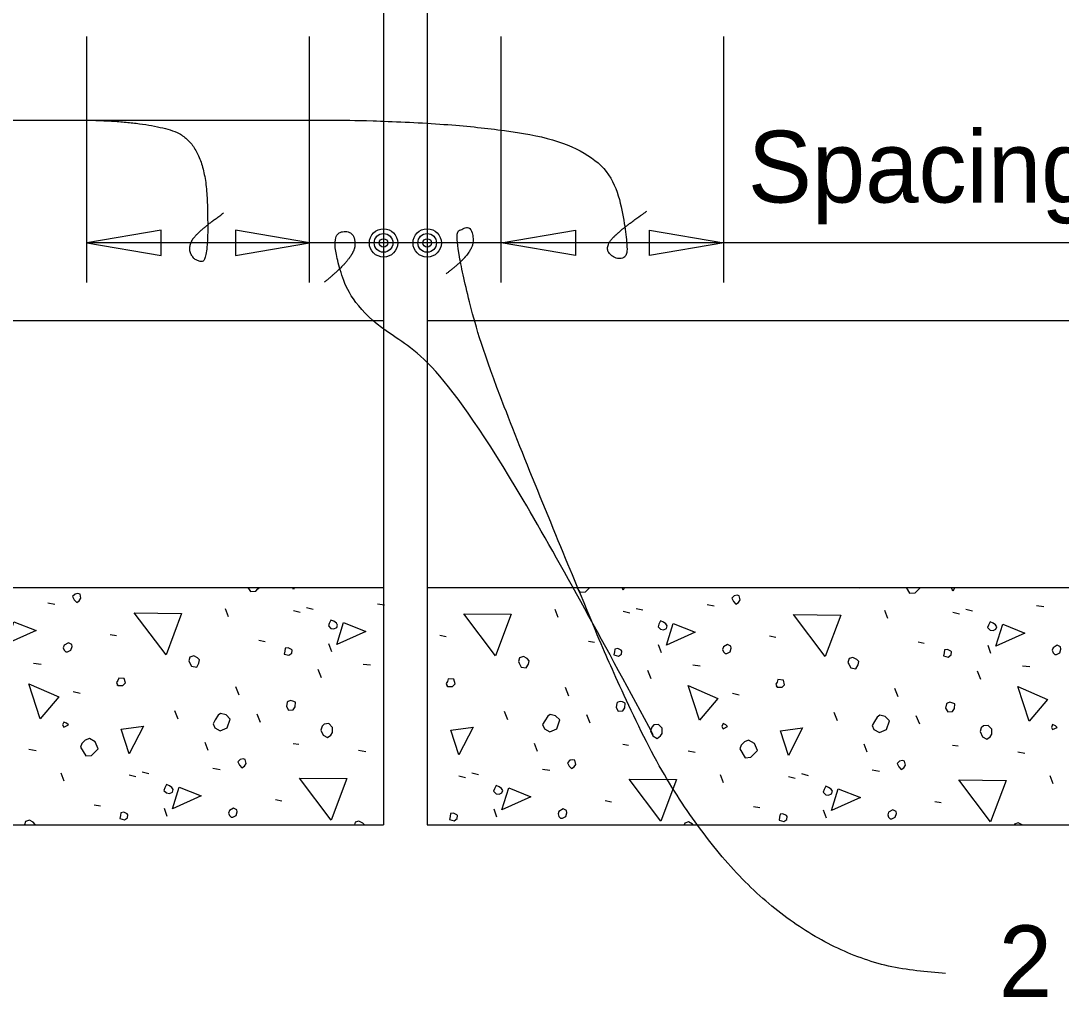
# Model space of a CAD drawing. Extents: x 0 to 20.5, y 0 to 13.
# Drawn here: x 12.283 to 13.744, y 8.997 to 10.367 of the extents above; entities that cross this region are included whole.
import ezdxf

# ---------------------------------------------------------------- set-up
doc = ezdxf.new("R2010")
doc.units = 0
for name, color, linetype in [('Dimension', 7, 'Continuous'), ('Miscellaneous', 7, 'Continuous'), ('TextStructures', 7, 'Continuous'), ('TrafBarrierConc', 7, 'Continuous')]:
    doc.layers.add(name, color=color, linetype=linetype)

msp = doc.modelspace()

# ---------------------------------------------------------------- linework, layer by layer
at = {"layer": 'Dimension'}
for p, q in [((12.3757, 9.9998), (12.3757, 10.3453)), ((12.6882, 9.9998), (12.6882, 10.3453)), ((12.9577, 9.9998), (12.9577, 10.3453)), ((13.2702, 9.9998), (13.2702, 10.3453)), ((15.3216, 10.0556), (12.3757, 10.0556))]:
    msp.add_line(p, q, dxfattribs=at)
for points in [[(12.3757, 10.0556), (12.4798, 10.038), (12.4798, 10.0733)], [(12.6882, 10.0556), (12.5841, 10.0733), (12.5841, 10.038)], [(12.9577, 10.0556), (13.0619, 10.0733), (13.0619, 10.038)], [(13.2702, 10.0556), (13.1661, 10.038), (13.1661, 10.0733)]]:
    msp.add_lwpolyline(points, close=True, dxfattribs=at)
for centre, radius in [((12.7923, 10.0556), 0.0199), ((12.8536, 10.0556), 0.0199), ((12.7923, 10.0556), 0.0131), ((12.7923, 10.0556), 0.00592), ((12.8536, 10.0556), 0.0131), ((12.8536, 10.0556), 0.00592)]:
    msp.add_circle(centre, radius, dxfattribs=at)
for points in [[(12.1713, 10.2281), (12.2987, 10.2281), (12.5124, 10.2281), (12.8773, 10.2281), (13.1083, 10.1892), (13.1396, 10.0428), (13.1234, 10.0299), (13.1018, 10.0461), (13.1212, 10.072), (13.1622, 10.1001)], [(12.3581, 10.2281), (12.4466, 10.2281), (12.5416, 10.1995), (12.5476, 10.0296), (12.5271, 10.0296), (12.5174, 10.0485), (12.5298, 10.0707), (12.5676, 10.0977)], [(13.1712, 9.3651), (12.9166, 9.8494), (12.7505, 9.9604), (12.7241, 10.0392), (12.7241, 10.0716), (12.7522, 10.0716), (12.7522, 10.0349), (12.709, 10.0004)], [(13.582, 9.0297), (13.2936, 9.0378), (12.9412, 9.859), (12.8911, 10.0619), (12.9019, 10.077), (12.9181, 10.077), (12.9181, 10.0403), (12.8803, 10.0123)]]:
    msp.add_open_spline(points, degree=2, dxfattribs=at)
at = {"layer": 'Miscellaneous'}
for p, q in [((13.4589, 9.5719), (13.4612, 9.5714)), ((13.7028, 9.5714), (13.7026, 9.5719)), ((12.3206, 9.5502), (12.3306, 9.5485)), ((12.7837, 9.549), (12.7937, 9.5473)), ((13.2468, 9.5479), (13.2568, 9.5461)), ((13.7098, 9.5467), (13.7199, 9.5449)), ((12.5746, 9.5308), (12.5704, 9.542)), ((12.6659, 9.5396), (12.6753, 9.5373)), ((12.6841, 9.5437), (12.6936, 9.5413)), ((13.0376, 9.5296), (13.0335, 9.5408)), ((13.129, 9.5384), (13.1384, 9.5361)), ((13.1472, 9.5425), (13.1566, 9.5402)), ((13.5007, 9.5284), (13.4966, 9.5396)), ((13.5921, 9.5373), (13.6015, 9.5349)), ((13.6103, 9.5413), (13.6197, 9.539)), ((12.4084, 9.506), (12.4172, 9.5043)), ((12.8715, 9.5049), (12.8803, 9.5031)), ((13.3346, 9.5037), (13.3434, 9.5019)), ((12.617, 9.4978), (12.6258, 9.496)), ((12.7195, 9.4813), (12.7154, 9.4925)), ((13.0801, 9.4966), (13.0889, 9.4948)), ((13.1826, 9.4801), (13.1784, 9.4913)), ((13.5432, 9.4954), (13.552, 9.4937)), ((13.6456, 9.479), (13.6415, 9.4902)), ((12.3006, 9.4654), (12.3112, 9.4642)), ((12.7053, 9.4448), (12.7006, 9.4566)), ((12.7636, 9.4642), (12.7742, 9.463)), ((13.2267, 9.463), (13.2373, 9.4618)), ((13.6898, 9.4618), (13.7004, 9.4607)), ((13.1684, 9.4436), (13.1637, 9.4554)), ((13.6315, 9.4424), (13.6268, 9.4542)), ((12.5893, 9.4206), (12.5846, 9.4324)), ((13.0524, 9.4194), (13.0477, 9.4312)), ((13.5155, 9.4182), (13.5107, 9.43)), ((12.3565, 9.4259), (12.366, 9.4235)), ((13.2827, 9.4235), (13.2921, 9.4212)), ((12.5039, 9.387), (12.4991, 9.3988)), ((12.6193, 9.3823), (12.6146, 9.3941)), ((12.9669, 9.3858), (12.9622, 9.3976)), ((13.0824, 9.3811), (13.0777, 9.3929)), ((13.43, 9.3846), (13.4253, 9.3964)), ((13.5455, 9.38), (13.5408, 9.3918)), ((12.2941, 9.3446), (12.3041, 9.3428)), ((12.5457, 9.3428), (12.5416, 9.354)), ((12.6653, 9.3529), (12.6735, 9.3517)), ((12.7572, 9.3434), (12.7672, 9.3417)), ((13.0088, 9.3416), (13.0046, 9.3528)), ((13.1284, 9.3517), (13.1366, 9.3505)), ((13.2203, 9.3423), (13.2303, 9.3405)), ((13.4719, 9.3405), (13.4677, 9.3516)), ((13.5914, 9.3505), (13.5997, 9.3493)), ((13.6834, 9.3411), (13.6934, 9.3393)), ((12.3436, 9.2998), (12.3395, 9.311)), ((12.4532, 9.3128), (12.4626, 9.3104)), ((12.5527, 9.3181), (12.5627, 9.3163)), ((12.9163, 9.3116), (12.9257, 9.3092)), ((13.0158, 9.3169), (13.0258, 9.3151)), ((13.3793, 9.3104), (13.3888, 9.308)), ((13.4789, 9.3157), (13.4889, 9.314)), ((12.4349, 9.3087), (12.4444, 9.3063)), ((12.898, 9.3075), (12.9075, 9.3051)), ((13.2698, 9.2975), (13.2656, 9.3087)), ((13.3611, 9.3063), (13.3705, 9.304)), ((13.7329, 9.2963), (13.7287, 9.3075)), ((12.386, 9.2668), (12.3949, 9.2651)), ((12.6405, 9.2739), (12.6494, 9.2721)), ((13.1036, 9.2727), (13.1124, 9.271)), ((13.5667, 9.2715), (13.5755, 9.2698)), ((12.4885, 9.2504), (12.4844, 9.2616)), ((12.9516, 9.2492), (12.9475, 9.2604)), ((13.3122, 9.2645), (13.321, 9.2627)), ((13.4147, 9.248), (13.4106, 9.2592))]:
    msp.add_line(p, q, dxfattribs=at)
for points in [[(12.3577, 9.5544), (12.3613, 9.5508), (12.3648, 9.5532), (12.3671, 9.5567), (12.366, 9.5626), (12.363, 9.5632), (12.3589, 9.5626), (12.3554, 9.5591), (12.3577, 9.5544)], [(12.6017, 9.5719), (12.6052, 9.5661), (12.6129, 9.5667), (12.6158, 9.5697), (12.618, 9.5719)], [(12.6659, 9.569), (12.665, 9.5719)], [(12.6673, 9.5719), (12.6659, 9.569)], [(13.064, 9.5719), (13.0683, 9.565), (13.0759, 9.5655), (13.0789, 9.5685), (13.0823, 9.5719)], [(13.1289, 9.5679), (13.1277, 9.5719)], [(13.131, 9.5719), (13.1289, 9.5679)], [(13.2839, 9.552), (13.2874, 9.5485), (13.291, 9.5508), (13.2933, 9.5544), (13.2921, 9.5602), (13.2892, 9.5608), (13.2851, 9.5602), (13.2815, 9.5567), (13.2839, 9.552)], [(13.5264, 9.5719), (13.5314, 9.5638), (13.539, 9.5644), (13.542, 9.5673), (13.5465, 9.5719)], [(13.592, 9.5667), (13.5904, 9.5719)], [(13.5947, 9.5719), (13.592, 9.5667)], [(12.4868, 9.4772), (12.442, 9.5361), (12.5086, 9.5355), (12.4868, 9.4772)], [(12.9498, 9.476), (12.9051, 9.5349), (12.9716, 9.5343), (12.9498, 9.476)], [(13.4129, 9.4748), (13.3681, 9.5337), (13.4347, 9.5331), (13.4129, 9.4748)], [(12.2634, 9.4931), (12.2729, 9.5237), (12.3041, 9.5113), (12.2634, 9.4931)], [(12.7183, 9.5142), (12.7224, 9.5137), (12.7266, 9.5154), (12.7277, 9.519), (12.726, 9.5219), (12.7224, 9.5243), (12.7183, 9.526), (12.7159, 9.5213), (12.7148, 9.5178), (12.7183, 9.5142)], [(12.7265, 9.4919), (12.7359, 9.5225), (12.7672, 9.5102), (12.7265, 9.4919)], [(13.1814, 9.5131), (13.1855, 9.5125), (13.1896, 9.5142), (13.1908, 9.5178), (13.189, 9.5207), (13.1855, 9.5231), (13.1814, 9.5249), (13.179, 9.5201), (13.1779, 9.5166), (13.1814, 9.5131)], [(13.1896, 9.4907), (13.199, 9.5214), (13.2303, 9.509), (13.1896, 9.4907)], [(13.6445, 9.5119), (13.6486, 9.5113), (13.6527, 9.5131), (13.6539, 9.5166), (13.6521, 9.5195), (13.6486, 9.5219), (13.6445, 9.5237), (13.6421, 9.519), (13.6409, 9.5154), (13.6445, 9.5119)], [(13.6527, 9.4895), (13.6621, 9.5202), (13.6933, 9.5078), (13.6527, 9.4895)], [(12.3459, 9.4813), (12.3483, 9.4813), (12.353, 9.4836), (12.3548, 9.4889), (12.3542, 9.4919), (12.3495, 9.4942), (12.3436, 9.4907), (12.3424, 9.4872), (12.3436, 9.4836), (12.3459, 9.4813)], [(12.6529, 9.4783), (12.6594, 9.4766), (12.6635, 9.4795), (12.6641, 9.4836), (12.663, 9.4848), (12.6582, 9.4872), (12.6541, 9.4866), (12.6535, 9.4825), (12.6529, 9.4783)], [(13.116, 9.4772), (13.1225, 9.4754), (13.1266, 9.4783), (13.1272, 9.4825), (13.126, 9.4836), (13.1213, 9.486), (13.1172, 9.4854), (13.1166, 9.4813), (13.116, 9.4772)], [(13.2721, 9.4789), (13.2745, 9.4789), (13.2792, 9.4813), (13.2809, 9.4866), (13.2803, 9.4895), (13.2756, 9.4919), (13.2697, 9.4884), (13.2686, 9.4848), (13.2697, 9.4813), (13.2721, 9.4789)], [(13.7352, 9.4777), (13.7375, 9.4777), (13.7422, 9.4801), (13.744, 9.4854), (13.7434, 9.4884), (13.7387, 9.4907), (13.7328, 9.4872), (13.7316, 9.4836), (13.7328, 9.4801), (13.7352, 9.4777)], [(12.5198, 9.4666), (12.5227, 9.4612), (12.5298, 9.4601), (12.5327, 9.4654), (12.5339, 9.4701), (12.531, 9.473), (12.5257, 9.476), (12.5204, 9.4742), (12.5186, 9.4689), (12.5198, 9.4666)], [(12.9828, 9.4654), (12.9858, 9.4601), (12.9929, 9.4589), (12.9958, 9.4642), (12.997, 9.4689), (12.994, 9.4719), (12.9887, 9.4748), (12.9834, 9.473), (12.9817, 9.4677), (12.9828, 9.4654)], [(13.4459, 9.4642), (13.4489, 9.4589), (13.4559, 9.4577), (13.4589, 9.463), (13.4601, 9.4677), (13.4571, 9.4707), (13.4518, 9.4736), (13.4465, 9.4719), (13.4447, 9.4666), (13.4459, 9.4642)], [(13.5791, 9.476), (13.5856, 9.4742), (13.5897, 9.4772), (13.5903, 9.4813), (13.5891, 9.4825), (13.5844, 9.4848), (13.5803, 9.4842), (13.5797, 9.4801), (13.5791, 9.476)], [(12.419, 9.4341), (12.4261, 9.4341), (12.4296, 9.4377), (12.4278, 9.4442), (12.4202, 9.4447), (12.419, 9.4412), (12.4172, 9.4383), (12.419, 9.4341), (12.4178, 9.4353)], [(12.8821, 9.433), (12.8892, 9.433), (12.8927, 9.4365), (12.8909, 9.443), (12.8833, 9.4436), (12.8821, 9.44), (12.8803, 9.4371), (12.8821, 9.433), (12.8809, 9.4341)], [(13.3452, 9.4318), (13.3522, 9.4318), (13.3558, 9.4353), (13.354, 9.4418), (13.3463, 9.4424), (13.3452, 9.4389), (13.3434, 9.4359), (13.3452, 9.4318), (13.344, 9.433)], [(12.31, 9.3876), (12.2941, 9.4365), (12.336, 9.4183), (12.31, 9.3876)], [(13.2362, 9.3853), (13.2203, 9.4342), (13.2621, 9.4159), (13.2362, 9.3853)], [(13.6993, 9.3841), (13.6834, 9.433), (13.7252, 9.4147), (13.6993, 9.3841)], [(12.6558, 9.4047), (12.6588, 9.3994), (12.6653, 9.4), (12.6682, 9.4041), (12.6688, 9.4106), (12.6647, 9.4124), (12.6617, 9.413), (12.6582, 9.4118), (12.657, 9.4106), (12.6558, 9.4047)], [(13.1189, 9.4035), (13.1219, 9.3982), (13.1284, 9.3988), (13.1313, 9.4029), (13.1319, 9.4094), (13.1278, 9.4112), (13.1248, 9.4118), (13.1213, 9.4106), (13.1201, 9.4094), (13.1189, 9.4035)], [(13.582, 9.4024), (13.585, 9.3971), (13.5914, 9.3976), (13.5944, 9.4018), (13.595, 9.4083), (13.5908, 9.41), (13.5879, 9.4106), (13.5844, 9.4094), (13.5832, 9.4083), (13.582, 9.4024)], [(12.5551, 9.3746), (12.5628, 9.3705), (12.5728, 9.3746), (12.5769, 9.387), (12.571, 9.3929), (12.5634, 9.3947), (12.5598, 9.3923), (12.5557, 9.3858), (12.5528, 9.3805), (12.5551, 9.3746)], [(13.0182, 9.3734), (13.0259, 9.3693), (13.0359, 9.3734), (13.04, 9.3858), (13.0341, 9.3917), (13.0264, 9.3935), (13.0229, 9.3911), (13.0188, 9.3846), (13.0158, 9.3793), (13.0182, 9.3734)], [(13.4813, 9.3723), (13.4889, 9.3681), (13.499, 9.3723), (13.5031, 9.3846), (13.4972, 9.3905), (13.4895, 9.3923), (13.486, 9.3899), (13.4819, 9.3835), (13.4789, 9.3782), (13.4813, 9.3723)], [(12.343, 9.3758), (12.3495, 9.3788), (12.3471, 9.3811), (12.343, 9.3829), (12.3413, 9.3788), (12.343, 9.3758)], [(12.4349, 9.3381), (12.4237, 9.3729), (12.4549, 9.377), (12.4349, 9.3381)], [(12.7042, 9.3717), (12.7077, 9.3646), (12.7136, 9.3611), (12.7183, 9.3646), (12.7207, 9.3682), (12.7207, 9.3753), (12.7154, 9.3806), (12.7089, 9.38), (12.7059, 9.377), (12.7042, 9.3717)], [(12.898, 9.3369), (12.8868, 9.3717), (12.918, 9.3758), (12.898, 9.3369)], [(13.1672, 9.3705), (13.1708, 9.3635), (13.1767, 9.3599), (13.1814, 9.3635), (13.1837, 9.367), (13.1837, 9.3741), (13.1784, 9.3794), (13.172, 9.3788), (13.169, 9.3758), (13.1672, 9.3705)], [(13.2692, 9.3735), (13.2757, 9.3764), (13.2733, 9.3788), (13.2692, 9.3806), (13.2674, 9.3764), (13.2692, 9.3735)], [(13.3611, 9.3357), (13.3499, 9.3705), (13.3811, 9.3746), (13.3611, 9.3357)], [(13.6303, 9.3694), (13.6339, 9.3623), (13.6398, 9.3588), (13.6445, 9.3623), (13.6468, 9.3658), (13.6468, 9.3729), (13.6415, 9.3782), (13.635, 9.3776), (13.6321, 9.3747), (13.6303, 9.3694)], [(13.7323, 9.3723), (13.7387, 9.3753), (13.7364, 9.3776), (13.7323, 9.3794), (13.7305, 9.3753), (13.7323, 9.3723)], [(12.3666, 9.3476), (12.3743, 9.3352), (12.3819, 9.3358), (12.3849, 9.3387), (12.3913, 9.3452), (12.3872, 9.3552), (12.379, 9.3599), (12.3731, 9.3576), (12.3684, 9.3529), (12.3666, 9.3476)], [(13.2928, 9.3452), (13.3004, 9.3328), (13.3081, 9.3334), (13.311, 9.3364), (13.3175, 9.3428), (13.3134, 9.3529), (13.3051, 9.3576), (13.2992, 9.3552), (13.2945, 9.3505), (13.2928, 9.3452)], [(12.5898, 9.3222), (12.5934, 9.3187), (12.5969, 9.321), (12.5993, 9.3246), (12.5981, 9.3305), (12.5951, 9.3311), (12.591, 9.3305), (12.5875, 9.3269), (12.5898, 9.3222)], [(13.0529, 9.321), (13.0565, 9.3175), (13.06, 9.3199), (13.0624, 9.3234), (13.0612, 9.3293), (13.0582, 9.3299), (13.0541, 9.3293), (13.0506, 9.3258), (13.0529, 9.321)], [(13.516, 9.3199), (13.5195, 9.3163), (13.5231, 9.3187), (13.5254, 9.3222), (13.5243, 9.3281), (13.5213, 9.3287), (13.5172, 9.3281), (13.5137, 9.3246), (13.516, 9.3199)], [(12.7189, 9.245), (12.6741, 9.304), (12.7407, 9.3034), (12.7189, 9.245)], [(13.182, 9.2438), (13.1372, 9.3028), (13.2038, 9.3022), (13.182, 9.2438)], [(13.6451, 9.2427), (13.6003, 9.3016), (13.6669, 9.301), (13.6451, 9.2427)], [(12.4874, 9.2833), (12.4915, 9.2827), (12.4956, 9.2845), (12.4968, 9.288), (12.495, 9.291), (12.4915, 9.2933), (12.4874, 9.2951), (12.485, 9.2904), (12.4838, 9.2868), (12.4874, 9.2833)], [(12.4956, 9.2609), (12.505, 9.2916), (12.5362, 9.2792), (12.4956, 9.2609)], [(12.9504, 9.2821), (12.9546, 9.2815), (12.9587, 9.2833), (12.9599, 9.2868), (12.9581, 9.2898), (12.9546, 9.2921), (12.9504, 9.2939), (12.9481, 9.2892), (12.9469, 9.2856), (12.9504, 9.2821)], [(12.9586, 9.2598), (12.9681, 9.2904), (12.9993, 9.278), (12.9586, 9.2598)], [(13.4135, 9.2809), (13.4176, 9.2803), (13.4218, 9.2821), (13.4229, 9.2856), (13.4212, 9.2886), (13.4176, 9.291), (13.4135, 9.2927), (13.4112, 9.288), (13.41, 9.2845), (13.4135, 9.2809)], [(13.4217, 9.2586), (13.4312, 9.2892), (13.4624, 9.2768), (13.4217, 9.2586)], [(12.422, 9.2474), (12.4285, 9.2456), (12.4326, 9.2486), (12.4332, 9.2527), (12.432, 9.2539), (12.4273, 9.2562), (12.4232, 9.2556), (12.4226, 9.2515), (12.422, 9.2474)], [(12.5781, 9.2492), (12.5804, 9.2492), (12.5851, 9.2515), (12.5869, 9.2568), (12.5863, 9.2598), (12.5816, 9.2621), (12.5757, 9.2586), (12.5745, 9.255), (12.5757, 9.2515), (12.5781, 9.2492)], [(12.8851, 9.2462), (12.8915, 9.2444), (12.8957, 9.2474), (12.8963, 9.2515), (12.8951, 9.2527), (12.8904, 9.255), (12.8862, 9.2545), (12.8857, 9.2503), (12.8851, 9.2462)], [(13.0411, 9.248), (13.0435, 9.248), (13.0482, 9.2503), (13.05, 9.2556), (13.0494, 9.2586), (13.0447, 9.2609), (13.0388, 9.2574), (13.0376, 9.2539), (13.0388, 9.2503), (13.0411, 9.248)], [(13.3481, 9.245), (13.3546, 9.2433), (13.3588, 9.2462), (13.3593, 9.2503), (13.3582, 9.2515), (13.3534, 9.2539), (13.3493, 9.2533), (13.3487, 9.2492), (13.3481, 9.245)], [(13.5042, 9.2468), (13.5066, 9.2468), (13.5113, 9.2492), (13.5131, 9.2545), (13.5125, 9.2574), (13.5078, 9.2598), (13.5019, 9.2562), (13.5007, 9.2527), (13.5019, 9.2492), (13.5042, 9.2468)], [(12.3028, 9.2385), (12.303, 9.2391), (12.3, 9.2421), (12.2947, 9.245), (12.2894, 9.2433), (12.2878, 9.2385)], [(12.7655, 9.2385), (12.7631, 9.2409), (12.7578, 9.2438), (12.7525, 9.2421), (12.7513, 9.2385)], [(13.2274, 9.2385), (13.2262, 9.2397), (13.2209, 9.2427), (13.2156, 9.2409), (13.2148, 9.2385)], [(13.6893, 9.2385), (13.6893, 9.2385), (13.6839, 9.2415), (13.6786, 9.2397), (13.6782, 9.2385)]]:
    msp.add_lwpolyline(points, dxfattribs=at)
at = {"layer": 'TrafBarrierConc'}
for p, q in [((12.7923, 10.9885), (12.7923, 9.9469)), ((12.8536, 10.9885), (12.8536, 9.9469)), ((10.4486, 9.9469), (12.7923, 9.9469)), ((12.7924, 9.9469), (12.7924, 9.2385)), ((12.8536, 9.9469), (15.4959, 9.9469)), ((12.8536, 9.9469), (12.8536, 9.2385)), ((10.4486, 9.5719), (12.7924, 9.5719)), ((12.8536, 9.5719), (15.4959, 9.5719)), ((10.4486, 9.2385), (12.7924, 9.2385)), ((12.8536, 9.2385), (15.4959, 9.2385))]:
    msp.add_line(p, q, dxfattribs=at)

# ---------------------------------------------------------------- texts
at = {"layer": 'Dimension'}
msp.add_text('2', height=0.1008, dxfattribs=at).set_placement((13.6565, 8.9966))
at = {"layer": 'TextStructures'}
msp.add_text('Spacing Pairs of Bars 4C', height=0.1008, dxfattribs=at).set_placement((13.3041, 10.1123))

doc.saveas('drawing.dxf')
